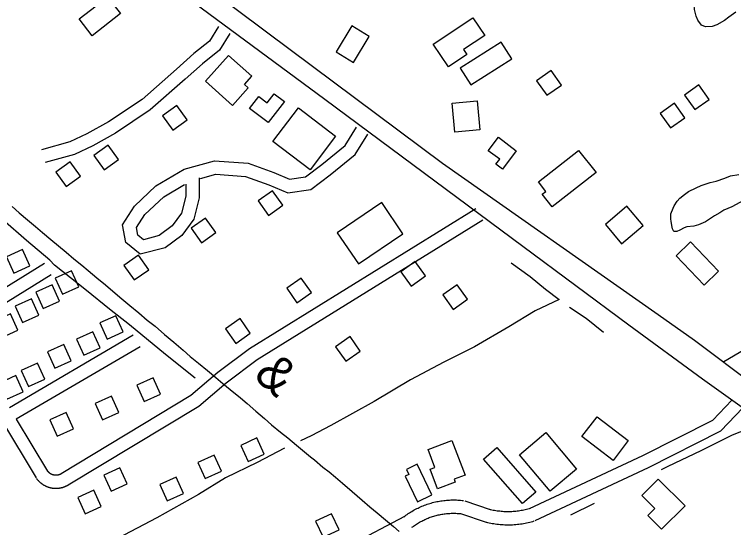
# Model space of a CAD drawing. Extents: x 3540316 to 3578335, y 553172 to 578787.
# Drawn here: x 3551062 to 3552683, y 568851 to 570007 of the extents above; entities that cross this region are included whole.
import ezdxf

# ---------------------------------------------------------------- set-up
doc = ezdxf.new("R2010")
doc.units = 0
for name, color, linetype in [('V-BLDG-OTLN', 7, 'Continuous'), ('V-RAIL-IDEN', 7, 'Continuous'), ('V-RAIL-TRAK', 7, 'Continuous'), ('V-ROAD-CNTR', 7, 'Continuous'), ('V-SITE-VEGE', 7, 'Continuous'), ('V-TOPO-SHOR', 7, 'Continuous')]:
    doc.layers.add(name, color=color, linetype=linetype)

msp = doc.modelspace()

# ---------------------------------------------------------------- linework, layer by layer
at = {"layer": 'V-BLDG-OTLN'}
for points in [[(3551207.7, 569996.7), (3551272.1, 570046.5), (3551301.3, 570008.7), (3551237, 569958.9)], [(3552006, 569939.6), (3552095.5, 569999.2), (3552121.9, 569959.6), (3552074.4, 569927.9), (3552082, 569916.5), (3552040, 569888.6)], [(3551822.6, 569981), (3551786.9, 569923), (3551826.1, 569898.9), (3551861.7, 569956.9)], [(3552158.9, 569944.8), (3552066.8, 569886.2), (3552090.8, 569848.5), (3552182.9, 569907.2)], [(3551492.6, 569856.8), (3551553.7, 569802), (3551588.8, 569841.2), (3551580.4, 569848.7), (3551597.2, 569867.5), (3551544.5, 569914.7)], [(3552262.2, 569824.7), (3552294.8, 569847.9), (3552271.6, 569880.5), (3552239, 569857.3)], [(3552595.3, 569792.4), (3552627.9, 569815.6), (3552604.7, 569848.2), (3552572.1, 569825.1)], [(3551633.9, 569763.1), (3551592.2, 569795.1), (3551613.1, 569822.3), (3551632, 569807.7), (3551647.8, 569828.2), (3551670.5, 569810.8)], [(3552105.3, 569812.3), (3552111.2, 569746.8), (3552054.5, 569741.8), (3552048.7, 569807.2)], [(3551418.9, 569746), (3551451.5, 569769.1), (3551428.3, 569801.7), (3551395.7, 569778.6)], [(3551786, 569732.3), (3551728.3, 569656.8), (3551644.3, 569720.9), (3551702, 569796.4)], [(3552540.4, 569751.1), (3552573, 569774.3), (3552549.8, 569806.9), (3552517.2, 569783.7)], [(3552152.8, 569730.1), (3552193.2, 569699.9), (3552162, 569658.3), (3552147.3, 569669.3), (3552155.7, 569680.5), (3552130.1, 569699.6)], [(3551264.2, 569656.7), (3551296.8, 569679.9), (3551273.6, 569712.5), (3551241, 569689.4)], [(3552372.8, 569650.5), (3552273.8, 569573.1), (3552251.4, 569601.7), (3552259.7, 569608.3), (3552243.1, 569629.5), (3552333.7, 569700.4)], [(3551178.6, 569619), (3551211.2, 569642.2), (3551188, 569674.8), (3551155.4, 569651.7)], [(3551634.4, 569554.1), (3551667, 569577.2), (3551643.9, 569609.8), (3551611.3, 569586.7)], [(3551890, 569583), (3551789.8, 569514.8), (3551837.5, 569444.7), (3551937.7, 569512.8)], [(3552442.5, 569574.6), (3552393.8, 569533.3), (3552430.2, 569490.3), (3552478.9, 569531.5)], [(3551483.7, 569492.4), (3551516.3, 569515.6), (3551493.1, 569548.2), (3551460.5, 569525)], [(3552553.3, 569463.2), (3552616.5, 569397), (3552649.2, 569428.3), (3552586, 569494.5)], [(3551060.8, 569424.1), (3551097.2, 569440.6), (3551080.7, 569477.1), (3551044.2, 569460.5)], [(3551332.2, 569408.6), (3551364.8, 569431.8), (3551341.6, 569464.4), (3551309, 569441.2)], [(3551955.9, 569394.7), (3551988.5, 569417.8), (3551965.4, 569450.5), (3551932.8, 569427.3)], [(3551170.6, 569376.3), (3551207, 569392.8), (3551190.4, 569429.3), (3551154, 569412.7)], [(3551698.9, 569357.3), (3551731.5, 569380.4), (3551708.3, 569413), (3551675.7, 569389.9)], [(3551127, 569344.4), (3551163.4, 569361), (3551146.9, 569397.4), (3551110.5, 569380.9)], [(3552050.6, 569342.2), (3552083.2, 569365.4), (3552060, 569398), (3552027.4, 569374.8)], [(3551080.4, 569312.9), (3551116.8, 569329.5), (3551100.3, 569365.9), (3551063.8, 569349.4)], [(3551033.4, 569279.1), (3551069.8, 569295.6), (3551053.3, 569332.1), (3551016.9, 569315.5)], [(3551271, 569275.3), (3551307.4, 569291.8), (3551290.9, 569328.2), (3551254.5, 569311.7)], [(3551561, 569265.7), (3551593.6, 569288.9), (3551570.5, 569321.5), (3551537.9, 569298.3)], [(3551218.6, 569239.1), (3551255, 569255.6), (3551238.5, 569292), (3551202, 569275.5)], [(3551809, 569225.4), (3551841.6, 569248.5), (3551818.4, 569281.2), (3551785.8, 569258)], [(3551153.3, 569210.1), (3551189.7, 569226.7), (3551173.2, 569263.1), (3551136.7, 569246.6)], [(3551093.9, 569168.6), (3551130.3, 569185.1), (3551113.8, 569221.5), (3551077.4, 569205)], [(3551045.4, 569140.4), (3551081.8, 569156.9), (3551065.3, 569193.4), (3551028.9, 569176.8)], [(3551354.8, 569134.9), (3551391.2, 569151.4), (3551374.7, 569187.8), (3551338.2, 569171.3)], [(3551260.9, 569093.8), (3551297.4, 569110.3), (3551280.8, 569146.8), (3551244.4, 569130.2)], [(3551158.5, 569056.8), (3551194.9, 569073.4), (3551178.4, 569109.8), (3551142, 569093.3)], [(3552375.3, 569100.6), (3552445.4, 569046.8), (3552411.2, 569002.2), (3552341.1, 569056)], [(3552260, 569064.7), (3552329.1, 568982.6), (3552269.7, 568932.6), (3552200.6, 569014.6)], [(3551588.6, 568999.6), (3551625, 569016.1), (3551608.5, 569052.6), (3551572.1, 569036)], [(3552015.7, 568937.9), (3551998.8, 568982.1), (3552009.6, 568986.3), (3551994.3, 569026.3), (3552048.1, 569046.8), (3552077.8, 568969.2), (3552053, 568959.7), (3552055.5, 568953.1)], [(3552149, 569031), (3552237.1, 568930.9), (3552207.3, 568904.7), (3552119.2, 569004.8)], [(3551492.1, 568961.1), (3551528.5, 568977.7), (3551512, 569014.1), (3551475.5, 568997.6)], [(3551279.9, 568932.6), (3551316.3, 568949.2), (3551299.8, 568985.6), (3551263.4, 568969.1)], [(3552002.9, 568924.3), (3551969.5, 568993.3), (3551945.5, 568981.6), (3551950.9, 568970.5), (3551942.8, 568966.6), (3551970.8, 568908.8)], [(3551406.4, 568911.2), (3551442.9, 568927.7), (3551426.3, 568964.1), (3551389.9, 568947.6)], [(3552513.2, 568959.9), (3552573.4, 568899.5), (3552520.4, 568846.8), (3552489.4, 568877.9), (3552505.1, 568893.6), (3552476, 568922.8)], [(3551221.2, 568881.9), (3551257.6, 568898.4), (3551241.1, 568934.8), (3551204.7, 568918.3)], [(3551757.7, 568828.8), (3551793.9, 568845.8), (3551776.9, 568882), (3551740.7, 568865)]]:
    msp.add_lwpolyline(points, close=True, dxfattribs=at)
at = {"layer": 'V-RAIL-TRAK'}
for points in [[(3551057.1, 569573.9), (3551073.1, 569560.1), (3551091.4, 569544.1), (3551109.8, 569529), (3551125.1, 569515.5), (3551144, 569499.8), (3551161.8, 569485.2), (3551178.7, 569471), (3551196.2, 569456.4), (3551213.8, 569441.9), (3551228.2, 569430.2), (3551248, 569413.8), (3551267.4, 569397.6), (3551283.6, 569383.6), (3551304.3, 569365.8), (3551322, 569351.4), (3551342.7, 569334.3), (3551361.6, 569318.4), (3551379, 569304.8), (3551400.3, 569286.1), (3551421.1, 569268.4), (3551442.4, 569250.6), (3551458.4, 569236.4), (3551476.8, 569221.3), (3551497.5, 569204.9), (3551515.8, 569189.1), (3551531.7, 569175.6), (3551548.2, 569162.1), (3551571.4, 569142.8), (3551586.7, 569130.6), (3551605.8, 569113.3), (3551625.4, 569096.8)], [(3551625.4, 569096.8), (3551641.8, 569082.2), (3551661.4, 569066), (3551678.2, 569052.7), (3551697.8, 569036.2), (3551711.6, 569024.8), (3551729.6, 569010.4), (3551738.4, 569003.2), (3551757.5, 568987), (3551771.2, 568976.2), (3551785.6, 568964.4), (3551801.4, 568950.7), (3551822.9, 568932), (3551845.9, 568912.5), (3551863.2, 568897.4), (3551879.7, 568883.6), (3551898.3, 568868.3), (3551916.6, 568853), (3551929.4, 568842.1)]]:
    msp.add_lwpolyline(points, dxfattribs=at)
at = {"layer": 'V-ROAD-CNTR'}
for points in [[(3546224.2, 572767), (3546505.2, 572702.3), (3546754.9, 572639.5), (3547049.8, 572556.4), (3547359.7, 572458.9), (3547631.9, 572365.7), (3547979.9, 572239.9), (3548381.5, 572074.4), (3548939.9, 571818.7), (3549319.6, 571607.8), (3549509.4, 571489.7), (3549968.7, 571189.7), (3550323.2, 570939.2), (3550684.8, 570671.1), (3550916.6, 570501.9), (3551237.1, 570262.2), (3551633.1, 569965.2), (3552027.1, 569672.1), (3552513.2, 569330.7), (3552594.9, 569273.2)], [(3552793.6, 569055.6), (3552612.4, 569185.3), (3552446.6, 569307), (3552207.6, 569484), (3551761.9, 569815.5), (3551304.9, 570153.2), (3550836.1, 570502.1), (3550673.7, 570623.7), (3550478.8, 570761.3), (3550301.7, 570882), (3550172.8, 570981.8), (3550045.4, 571073.6), (3549908.5, 571174.3), (3549711.9, 571304.1), (3549627.5, 571363.1), (3549514.2, 571439.9)], [(3551522, 569979.6), (3551501.7, 569946.7), (3551466.8, 569918.8), (3551427.4, 569883.5), (3551349.8, 569815.6), (3551274.5, 569764.7), (3551225.5, 569737.6), (3551187.1, 569720), (3551123.2, 569701.8)], [(3551547.5, 569963.9), (3551524.5, 569926.5), (3551486.2, 569895.9), (3551447.2, 569861), (3551368.2, 569791.8), (3551290.1, 569739.1), (3551239.1, 569710.9), (3551197.5, 569691.7), (3551131.3, 569673)], [(3551478.4, 569638.8), (3551478.4, 569594), (3551466.5, 569545.9), (3551439.3, 569509.1), (3551401.8, 569480.9), (3551345.7, 569466.6), (3551313, 569493.2), (3551306, 569532.8), (3551332.5, 569575.3), (3551381, 569620.4), (3551445, 569658.2), (3551512.7, 569677), (3551589.1, 569671.7), (3551646.5, 569650.9), (3551682.2, 569635.7), (3551718.4, 569641.2), (3551755.2, 569668.9), (3551807.2, 569711.5), (3551833.4, 569752.9)], [(3551481.1, 569637.1), (3551515.8, 569646.7), (3551582.8, 569642.1), (3551635.5, 569623), (3551678.3, 569604.8), (3551730.4, 569612.7), (3551773.7, 569645.3), (3551830, 569691.3), (3551858.8, 569736.8)], [(3551448.4, 569624.2), (3551448.4, 569597.7), (3551438.8, 569558.9), (3551417.7, 569530.5), (3551388.5, 569508.5), (3551352.9, 569499.4), (3551340.6, 569509.5), (3551337.5, 569526.7), (3551355.9, 569556), (3551399.1, 569596.2), (3551445.6, 569623.7)], [(3551167.7, 568972.3), (3551459.8, 569149), (3551520.6, 569200.7), (3551592.2, 569253.9), (3552101.8, 569569.6)], [(3551183.2, 568946.7), (3551477.4, 569124.6), (3551539.3, 569177.2), (3551609.1, 569229.1), (3552117.6, 569544.1)], [(3550929, 569322.6), (3551129.6, 569446.6)], [(3550944.5, 569296.9), (3551145.3, 569421)], [(3552661, 569224.6), (3552823.3, 569320.4), (3552793.3, 569372.9)], [(3551330.1, 569284.1), (3551050.8, 569120.6)], [(3552594.9, 569273.2), (3552730.7, 569170.5), (3552956.8, 568997.2), (3553285.4, 568751.6), (3553734.6, 568421.7)], [(3551345.3, 569258.2), (3551066.3, 569094.9)], [(3550951.9, 569226.4), (3551111, 568962.7)], [(3552222.9, 568893.7), (3552478.2, 569013.3), (3552635.8, 569092.9), (3552678.7, 569137.9)], [(3552235.7, 568866.5), (3552491.3, 568986.4), (3552654, 569068.4), (3552703.3, 569120.3)], [(3551066.3, 569094.9), (3551136.6, 568978.2)], [(3551135.8, 568979.4), (3551136.2, 568979), (3551136.4, 568978.7), (3551136.7, 568978.3), (3551137, 568978), (3551137.2, 568977.7), (3551137.5, 568977.3), (3551137.8, 568977), (3551138.1, 568976.7), (3551138.4, 568976.4), (3551138.7, 568976.1), (3551139.1, 568975.8), (3551139.4, 568975.5), (3551139.7, 568975.2), (3551140, 568975), (3551140.4, 568974.7), (3551140.7, 568974.4), (3551141, 568974.1), (3551141.4, 568973.9), (3551141.7, 568973.7), (3551142.1, 568973.4), (3551142.4, 568973.2), (3551142.8, 568972.9), (3551143.2, 568972.7), (3551143.5, 568972.5), (3551143.9, 568972.3), (3551144.3, 568972.1), (3551144.7, 568971.9), (3551145.1, 568971.7), (3551145.4, 568971.5), (3551145.9, 568971.3), (3551146.3, 568971.2), (3551146.6, 568971), (3551147, 568970.9), (3551147.5, 568970.7), (3551147.9, 568970.6), (3551148.2, 568970.4), (3551148.7, 568970.3), (3551149.1, 568970.2), (3551149.5, 568970.1), (3551149.9, 568970), (3551150.3, 568969.9), (3551150.8, 568969.8), (3551151.2, 568969.7), (3551151.6, 568969.6), (3551152, 568969.5), (3551152.5, 568969.5), (3551152.9, 568969.4), (3551153.3, 568969.4), (3551153.8, 568969.3), (3551154.2, 568969.3), (3551154.6, 568969.3), (3551155, 568969.3), (3551155.5, 568969.3), (3551155.9, 568969.3), (3551156.3, 568969.3), (3551156.7, 568969.3), (3551157.2, 568969.3), (3551157.6, 568969.3), (3551158, 568969.4), (3551158.5, 568969.4), (3551158.9, 568969.5), (3551159.3, 568969.5), (3551159.7, 568969.6), (3551160.2, 568969.6), (3551160.6, 568969.7), (3551161, 568969.8), (3551161.4, 568969.9), (3551161.9, 568970), (3551162.3, 568970.1), (3551162.7, 568970.2), (3551163.1, 568970.4), (3551163.5, 568970.5), (3551163.9, 568970.6), (3551164.3, 568970.8), (3551164.7, 568970.9), (3551165.1, 568971.1), (3551165.5, 568971.3), (3551165.9, 568971.4), (3551166.3, 568971.6), (3551166.7, 568971.8), (3551167.1, 568972), (3551167.5, 568972.2), (3551167.8, 568972.4), (3551168, 568972.5)], [(3551111.8, 568961.5), (3551112.3, 568960.8), (3551112.9, 568960), (3551113.4, 568959.3), (3551114.1, 568958.6), (3551114.7, 568957.8), (3551115.3, 568957.2), (3551116, 568956.5), (3551116.6, 568955.7), (3551117.3, 568955.1), (3551118, 568954.4), (3551118.7, 568953.8), (3551119.4, 568953.1), (3551120.1, 568952.5), (3551120.9, 568951.9), (3551121.6, 568951.3), (3551122.3, 568950.7), (3551123.1, 568950.1), (3551123.8, 568949.5), (3551124.6, 568949), (3551125.4, 568948.5), (3551126.2, 568947.9), (3551127, 568947.4), (3551127.8, 568946.9), (3551128.7, 568946.4), (3551129.5, 568946), (3551130.3, 568945.5), (3551131.2, 568945.1), (3551132, 568944.7), (3551132.9, 568944.2), (3551133.8, 568943.9), (3551134.6, 568943.5), (3551135.5, 568943.1), (3551136.4, 568942.8), (3551137.3, 568942.5), (3551138.2, 568942.1), (3551139.2, 568941.8), (3551140, 568941.6), (3551140.9, 568941.3), (3551141.9, 568941), (3551142.8, 568940.8), (3551143.7, 568940.6), (3551144.7, 568940.4), (3551145.6, 568940.2), (3551146.6, 568940), (3551147.5, 568939.9), (3551148.4, 568939.8), (3551149.4, 568939.6), (3551150.3, 568939.5), (3551151.2, 568939.4), (3551152.2, 568939.4), (3551153.2, 568939.3), (3551154.2, 568939.3), (3551155.1, 568939.3), (3551156, 568939.3), (3551157, 568939.3), (3551158, 568939.3), (3551158.9, 568939.3), (3551159.8, 568939.4), (3551160.8, 568939.5), (3551161.8, 568939.6), (3551162.7, 568939.7), (3551163.6, 568939.8), (3551164.6, 568940), (3551165.5, 568940.1), (3551166.5, 568940.3), (3551167.4, 568940.5), (3551168.3, 568940.7), (3551169.2, 568940.9), (3551170.2, 568941.2), (3551171.1, 568941.4), (3551172, 568941.7), (3551172.9, 568942), (3551173.8, 568942.3), (3551174.7, 568942.6), (3551175.6, 568943), (3551176.5, 568943.3), (3551177.3, 568943.7), (3551178.3, 568944.1), (3551179.1, 568944.5), (3551180, 568944.9), (3551180.8, 568945.3), (3551181.6, 568945.8), (3551182.5, 568946.2), (3551182.9, 568946.5)], [(3551939.9, 568875.2), (3551941.7, 568876.7), (3551944.3, 568878.6), (3551946.9, 568880.4), (3551949.5, 568882.2), (3551952.2, 568883.9), (3551954.9, 568885.6), (3551957.7, 568887.3), (3551960.4, 568888.9), (3551963.1, 568890.4), (3551966, 568892), (3551968.8, 568893.4), (3551971.7, 568894.8), (3551974.6, 568896.2), (3551977.5, 568897.5), (3551980.4, 568898.8), (3551983.3, 568900), (3551986.3, 568901.1), (3551989.3, 568902.2), (3551992.3, 568903.3), (3551995.4, 568904.3), (3551998.4, 568905.2), (3552001.5, 568906.1), (3552004.5, 568907), (3552007.6, 568907.8), (3552010.8, 568908.5), (3552013.8, 568909.2), (3552017, 568909.8), (3552020.1, 568910.4), (3552023.3, 568910.9), (3552026.4, 568911.3), (3552029.6, 568911.7), (3552032.7, 568912.1), (3552036, 568912.4), (3552039.1, 568912.6), (3552042.3, 568912.8), (3552045.5, 568912.9), (3552048.6, 568913), (3552051.9, 568913), (3552055.1, 568913), (3552058.2, 568912.9), (3552061.4, 568912.7), (3552064.6, 568912.5), (3552067.7, 568912.2), (3552070.9, 568911.9), (3552074, 568911.6)], [(3552077, 568910.9), (3552134.4, 568891.8)], [(3552133.1, 568892.1), (3552135.3, 568891.6), (3552138.3, 568891), (3552141.3, 568890.3), (3552144.2, 568889.8), (3552147.2, 568889.3), (3552150.2, 568888.8), (3552153.2, 568888.4), (3552156.2, 568888.1), (3552159.2, 568887.8), (3552162.2, 568887.5), (3552165.2, 568887.3), (3552168.3, 568887.2), (3552171.3, 568887.1), (3552174.3, 568887), (3552177.3, 568887.1), (3552180.3, 568887.1), (3552183.4, 568887.3), (3552186.4, 568887.4), (3552189.4, 568887.6), (3552192.4, 568887.9), (3552195.4, 568888.3), (3552198.4, 568888.7), (3552201.4, 568889.1), (3552204.4, 568889.6), (3552207.4, 568890.1), (3552210.4, 568890.7), (3552213.3, 568891.3), (3552216.2, 568892.1), (3552219.2, 568892.8), (3552222.1, 568893.6), (3552225.1, 568894.5)], [(3550124.8, 567946.9), (3551329.8, 568553.5), (3551941.9, 568876.5)], [(3551958, 568851.3), (3551959.7, 568852.6), (3551961.8, 568854.2), (3551964, 568855.7), (3551966.2, 568857.2), (3551968.5, 568858.7), (3551970.7, 568860.1), (3551973, 568861.5), (3551975.3, 568862.8), (3551977.7, 568864.2), (3551980, 568865.4), (3551982.3, 568866.6), (3551984.8, 568867.8), (3551987.1, 568869), (3551989.6, 568870), (3551992, 568871.1), (3551994.5, 568872.1), (3551997, 568873.1), (3551999.4, 568874), (3552002, 568874.9), (3552004.5, 568875.7), (3552007.1, 568876.5), (3552009.6, 568877.3), (3552012.2, 568878), (3552014.8, 568878.6), (3552017.4, 568879.2), (3552020, 568879.8), (3552022.6, 568880.3), (3552025.2, 568880.8), (3552027.8, 568881.2), (3552030.5, 568881.6), (3552033.2, 568881.9), (3552035.8, 568882.2), (3552038.4, 568882.5), (3552041.1, 568882.7), (3552043.7, 568882.8), (3552046.4, 568882.9), (3552049.1, 568883), (3552051.7, 568883), (3552054.4, 568883), (3552057.1, 568882.9), (3552059.7, 568882.8), (3552062.4, 568882.6), (3552065.1, 568882.4), (3552067.7, 568882.1), (3552070.4, 568881.8)], [(3552067.5, 568882.4), (3552124.9, 568863.3)], [(3552126.2, 568863), (3552128.5, 568862.4), (3552131.9, 568861.6), (3552135.4, 568860.9), (3552138.9, 568860.3), (3552142.4, 568859.7), (3552145.9, 568859.1), (3552149.5, 568858.6), (3552153, 568858.2), (3552156.5, 568857.9), (3552160, 568857.6), (3552163.6, 568857.4), (3552167.1, 568857.2), (3552170.7, 568857.1), (3552174.2, 568857), (3552177.8, 568857.1), (3552181.3, 568857.2), (3552184.8, 568857.3), (3552188.4, 568857.5), (3552192, 568857.8), (3552195.5, 568858.1), (3552199, 568858.5), (3552202.5, 568858.9), (3552206, 568859.4), (3552209.5, 568860), (3552213, 568860.7), (3552216.4, 568861.3), (3552219.9, 568862.1), (3552223.4, 568862.9), (3552226.8, 568863.8), (3552230.2, 568864.7), (3552233.6, 568865.7)]]:
    msp.add_lwpolyline(points, dxfattribs=at)
at = {"layer": 'V-SITE-VEGE'}
for points in [[(3552688.2, 570012.1), (3552671.9, 570000.9), (3552662.2, 569993.2), (3552645.4, 569983.6), (3552634.6, 569979.7), (3552619.3, 569978.9), (3552610.5, 569983.1), (3552602.1, 569994), (3552598.7, 570003.2), (3552594.7, 570018.4), (3552594, 570028.8), (3552594.4, 570039.2), (3552596.5, 570047.4), (3552606.7, 570060.6), (3552614.7, 570072.2), (3552622.1, 570089.8), (3552624.7, 570096.4), (3552630.8, 570129.2), (3552636, 570149.5), (3552642.3, 570164.9), (3552655.1, 570186.4), (3552663.1, 570198.5), (3552675.5, 570213.4), (3552684.7, 570219.6)], [(3552572.2, 569601.4), (3552581.4, 569608.1), (3552598.2, 569616.6), (3552609.6, 569621.6), (3552629.7, 569627.9), (3552643.3, 569631.4), (3552663.4, 569638.2), (3552675.9, 569643.3), (3552694.4, 569646.3)], [(3552713.8, 569592), (3552679.1, 569573.5), (3552661.2, 569565.6), (3552652, 569560), (3552640.1, 569553.3), (3552619.5, 569539.9), (3552603.8, 569532.5), (3552592.9, 569530.2), (3552577.6, 569528.3), (3552571.6, 569526.1), (3552561.4, 569520.5), (3552554.8, 569517.6), (3552548.3, 569517.6), (3552545.5, 569524.1), (3552543.7, 569531.7), (3552541.9, 569541.5), (3552541.3, 569545.3), (3552541.7, 569557.3), (3552542.8, 569561.2), (3552548.6, 569576), (3552555.5, 569585.9), (3552562, 569593.1), (3552572.2, 569601.4)]]:
    msp.add_lwpolyline(points, dxfattribs=at)
at = {"layer": 'V-TOPO-SHOR'}
msp.add_line((3552368.9, 568905.3), (3552315, 568878.6), dxfattribs=at)
for points in [[(3551469.3, 569187.7), (3551402.7, 569240.5), (3551321.7, 569307.7), (3551276.1, 569342.7), (3551224.7, 569385.1), (3551152.5, 569442.3), (3551141.8, 569453.3), (3551089.1, 569497.7), (3551035.7, 569543.9), (3550982.6, 569589.5), (3550919.1, 569641), (3550871.6, 569681.4), (3550803.3, 569734.5), (3550752.5, 569779.8), (3550712.3, 569812.5), (3550693.1, 569825.8)], [(3552181.3, 569447.1), (3552224.7, 569416.1), (3552259, 569387.6), (3552289.7, 569364.6)], [(3552289.7, 569364.6), (3552235.7, 569339), (3552176.5, 569302.8), (3552098.8, 569257.8), (3552030.2, 569223.5), (3551954.8, 569183.7), (3551872.7, 569134.8), (3551775.3, 569081.1), (3551730.6, 569057.1), (3551707, 569046.4)], [(3552389.7, 569290.5), (3552350.6, 569321.6), (3552313, 569346.8)], [(3553172.3, 568724.4), (3553133.9, 568751.3), (3553066, 568800.6), (3553023.2, 568833.8), (3552965.9, 568874.4), (3552901.1, 568922.7), (3552848.7, 568960.8), (3552798.5, 568999.2), (3552758.5, 569028.1), (3552716, 569058.7), (3552708.3, 569064.6), (3552698.7, 569066.2), (3552678.2, 569058.4), (3552608.8, 569024), (3552534.7, 568988), (3552519.8, 568981.2)], [(3551670.8, 569029.3), (3551609, 568997.2), (3551538.1, 568963.2), (3551476.9, 568925), (3551383.4, 568872.9), (3551264.7, 568810.1), (3551175.7, 568756.4), (3551148.5, 568742.8), (3551117.5, 568730.8)]]:
    msp.add_lwpolyline(points, dxfattribs=at)

# ---------------------------------------------------------------- texts
at = {"layer": 'V-RAIL-IDEN'}
msp.add_text('&', height=83, rotation=318.9454, dxfattribs=at).set_placement((3551598.4, 569189.8))

doc.saveas('drawing.dxf')
